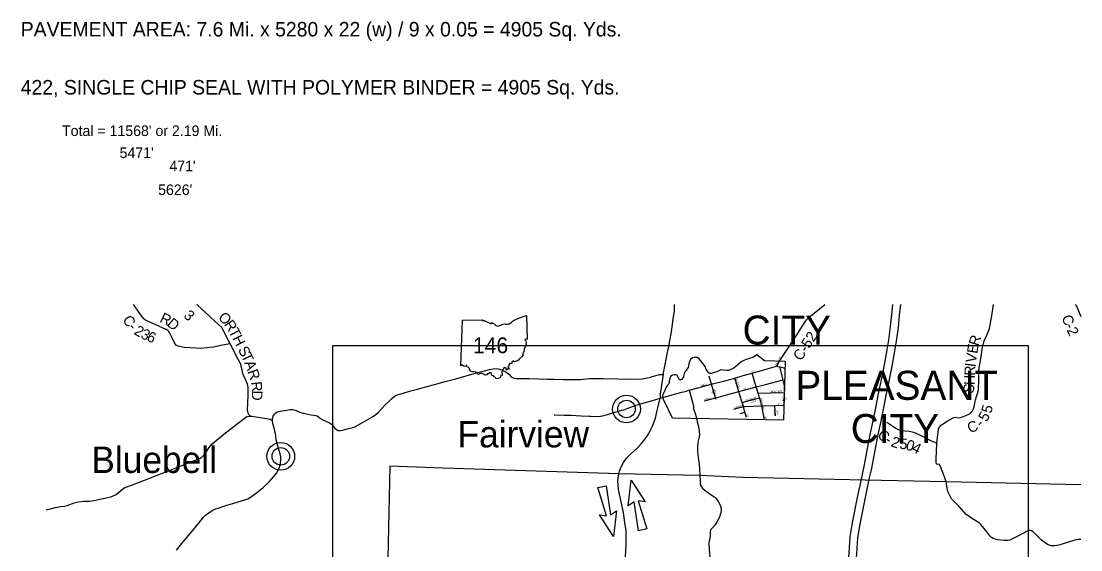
# Model space of a CAD drawing. Extents: x -452339 to 6403467, y -1 to 1814750.
# Drawn here: x 36134 to 96309, y 1629997 to 1660005 of the extents above; entities that cross this region are included whole.
import ezdxf

# ---------------------------------------------------------------- set-up
doc = ezdxf.new("R2010")
doc.units = 0
for name, color, linetype in [('Default', 7, 'Continuous'), ('GM_X_Adjacent_County_Text', 7, 'Continuous'), ('GM_X_County', 7, 'Continuous'), ('GM_X_County_Road', 7, 'Continuous'), ('GM_X_County_Road_Text', 7, 'Continuous'), ('GM_X_Minor_Lake', 7, 'Continuous'), ('GM_X_Minor_River', 7, 'Continuous'), ('GM_X_Minor_River_Text', 7, 'Continuous'), ('GM_X_Section_Text', 7, 'Continuous')]:
    doc.layers.add(name, color=color, linetype=linetype)

msp = doc.modelspace()

# ---------------------------------------------------------------- linework, layer by layer
at = {"layer": 'Default'}
for p, q in [((61109, 1640448), (61193, 1643031)), ((53831, 1602105), (53831, 1641599)), ((53831, 1641599), (93325, 1641599)), ((93325, 1641599), (93325, 1602105)), ((70605, 1632494), (70778, 1633955)), ((70778, 1633955), (71573, 1632718)), ((68885, 1633528), (69347, 1633635)), ((69372, 1631934), (68885, 1633528)), ((69347, 1633635), (69606, 1631987)), ((70941, 1632721), (70605, 1632494)), ((71200, 1631074), (70941, 1632721)), ((71573, 1632718), (71173, 1632774)), ((71173, 1632774), (71662, 1631180)), ((69768, 1630753), (68973, 1631991)), ((68973, 1631991), (69372, 1631934)), ((69606, 1631987), (69940, 1632213)), ((69940, 1632213), (69768, 1630753)), ((71662, 1631180), (71200, 1631074))]:
    msp.add_line(p, q, dxfattribs=at)
for points in [[(48004, 1641692), (47778, 1641649), (47475, 1641598), (47048, 1641504), (46704, 1641469), (46345, 1641431), (46062, 1641436), (45400, 1641486), (45045, 1641560), (44962, 1641600), (44858, 1641708), (44688, 1642065), (44573, 1642301), (44522, 1642390), (44470, 1642442), (44374, 1642494), (43188, 1643039), (43100, 1643111), (42961, 1643288), (42511, 1643927)], [(49155, 1637583), (49065, 1637680), (49017, 1637756), (48994, 1637916), (49020, 1638748), (49018, 1639208), (48987, 1639392), (48884, 1639621), (48737, 1639957), (48659, 1640298), (48584, 1640566), (48441, 1640839), (48004, 1641692), (47601, 1642470), (47530, 1642614), (47355, 1642775), (46401, 1643651), (46104, 1643927)], [(79219, 1640744), (79560, 1641260), (80079, 1642054), (80574, 1642824), (80729, 1643050), (80866, 1643177), (81773, 1643927)], [(88665, 1633859), (88577, 1634139), (88341, 1634720), (88269, 1634863), (88136, 1634833), (88093, 1634926), (88088, 1635126), (88134, 1636049), (88231, 1636836), (88268, 1636932), (88402, 1637086), (88719, 1637307), (89052, 1637491), (89152, 1637518), (89264, 1637504), (89419, 1637490), (89587, 1637549), (89960, 1637700), (90068, 1637783), (90153, 1637894), (90214, 1638009), (90281, 1638216), (90336, 1638512), (90494, 1639063), (90527, 1639712), (90527, 1640133), (90544, 1640343), (90603, 1640605), (90645, 1640975), (90721, 1641497), (90755, 1641657), (90830, 1641860), (90965, 1642180), (91032, 1642306), (91117, 1642567), (91251, 1643283), (91345, 1643927)], [(95995, 1643927), (96039, 1643881), (96091, 1643783), (96309, 1643236)], [(61193, 1643031), (62337, 1643047), (62320, 1643016), (62427, 1643010), (62542, 1642954), (62639, 1642920), (62758, 1642838), (62829, 1642838), (62859, 1642906), (62913, 1642854), (62978, 1642845), (63090, 1642721), (63182, 1642694), (63293, 1642737), (63374, 1642744), (63435, 1642785), (63592, 1642821), (63636, 1642800), (63719, 1642805), (63761, 1642820), (63834, 1642806), (63961, 1642900), (64092, 1643010), (64295, 1643115), (64596, 1643214), (64836, 1643302), (64870, 1641962)], [(64870, 1641962), (64835, 1641943), (64780, 1641952), (64744, 1641915), (64789, 1641852), (64810, 1641786), (64791, 1641713), (64810, 1641653), (64798, 1641602), (64763, 1641552), (64751, 1641504), (64722, 1641454), (64724, 1641425), (64696, 1641404), (64701, 1641319), (64687, 1641273), (64692, 1641233), (64646, 1641223), (64657, 1641189), (64628, 1641163), (64634, 1641120), (64601, 1641091), (64633, 1641035), (64608, 1641017), (64587, 1640949), (64528, 1640935), (64413, 1640811), (64371, 1640763), (64325, 1640751), (64299, 1640703), (64243, 1640703), (64156, 1640669), (64101, 1640727), (64004, 1640657), (63992, 1640576), (63870, 1640579), (63874, 1640538), (63847, 1640527), (63822, 1640486), (63836, 1640413), (63778, 1640395), (63785, 1640353), (63823, 1640328), (63839, 1640247), (63778, 1640263), (63728, 1640195), (63676, 1640211), (63692, 1640268), (63605, 1640338), (63523, 1640283), (63480, 1640194), (63479, 1640134), (63417, 1640098), (63457, 1640015), (63450, 1639957), (63451, 1639901), (63374, 1639904), (63327, 1639755)], [(63327, 1639755), (63194, 1639727), (63102, 1639710), (63069, 1639777), (63003, 1639813), (62959, 1639880), (62864, 1639890), (62841, 1639983), (62831, 1640058), (62701, 1640040), (62665, 1639994), (62619, 1639981), (62592, 1639935), (62529, 1639931), (62461, 1639909), (62417, 1639954), (62306, 1640000), (62256, 1640024), (62152, 1639988), (62130, 1639944), (62048, 1639963), (62028, 1640012), (61978, 1640026), (61967, 1640077), (61860, 1640105), (61778, 1640094), (61633, 1640135), (61624, 1640203), (61575, 1640286), (61550, 1640343), (61459, 1640386), (61440, 1640454), (61411, 1640453), (61384, 1640425), (61282, 1640412), (61242, 1640440), (61185, 1640488), (61109, 1640448)], [(70081, 1634303), (70120, 1634463), (70215, 1634704), (70336, 1634949), (70516, 1635200), (70731, 1635430), (71117, 1635766), (71337, 1636006), (71538, 1636247), (71708, 1636487), (71854, 1636742), (71988, 1637018), (72151, 1637464), (72234, 1637828), (72285, 1638049), (72430, 1638598)], [(70460, 1637986), (70540, 1638015), (71060, 1638201), (72178, 1638526), (72430, 1638598)], [(66393, 1637662), (66445, 1637657), (66979, 1637647), (67369, 1637631), (67928, 1637609), (68389, 1637590), (68457, 1637588), (68939, 1637572), (69038, 1637577), (69059, 1637578), (69291, 1637644), (70247, 1637917), (70320, 1637938), (70349, 1637947), (70460, 1637986)], [(37545, 1632284), (37617, 1632291), (37873, 1632339), (38068, 1632392), (38381, 1632453), (38592, 1632478), (38751, 1632510), (39141, 1632661), (39373, 1632722), (39714, 1632756), (40023, 1632756), (40259, 1632797), (40600, 1632878), (41047, 1632959), (41291, 1633025), (41535, 1633130), (41779, 1633350), (41982, 1633521), (42453, 1633688), (44498, 1634480), (46292, 1635198), (46404, 1635269), (46560, 1635449), (46741, 1635698), (46812, 1635796), (46977, 1636011), (47633, 1636553), (48721, 1637397), (48948, 1637556), (49060, 1637588), (49155, 1637583)], [(49155, 1637583), (49224, 1637579), (50061, 1637457)], [(50061, 1637457), (50065, 1637456), (50248, 1637411), (50405, 1637335)], [(85301, 1637235), (85808, 1636893), (85931, 1636820), (86121, 1636769), (86324, 1636751), (86583, 1636728), (86802, 1636677), (87068, 1636566), (87726, 1636222), (88134, 1636049)], [(70407, 1628954), (70498, 1630258), (70482, 1631065), (70417, 1631541), (70336, 1632117), (70063, 1633422), (70030, 1633700), (70026, 1633888), (70041, 1634073), (70081, 1634303)], [(96309, 1630588), (96302, 1630589), (96166, 1630579), (95962, 1630549), (95069, 1630265), (94825, 1630220), (94633, 1630225), (94422, 1630300), (94078, 1630551), (93595, 1631008), (93504, 1631073), (93452, 1631098), (93396, 1631102), (93300, 1631075), (92666, 1630733), (92353, 1630576), (92281, 1630549), (92165, 1630534), (91934, 1630532), (91575, 1630572), (91336, 1630634), (91241, 1630691), (91134, 1630792), (90913, 1631090), (90716, 1631345), (90637, 1631433), (90530, 1631523), (90253, 1631693), (89935, 1631897), (89797, 1632010), (89666, 1632159), (89402, 1632446), (88959, 1632899), (88759, 1633298), (88740, 1633373), (88729, 1633494), (88705, 1633632), (88665, 1633859)]]:
    msp.add_lwpolyline(points, dxfattribs=at)
at = {"layer": 'GM_X_County_Road'}
for points in [[(72877, 1641384), (72888, 1641441), (73064, 1642369), (73169, 1643096), (73230, 1643569), (73226, 1643927)], [(83847, 1633999), (84004, 1634725), (84181, 1635626), (84354, 1636536), (84520, 1637315), (84663, 1638065), (84822, 1638854), (84988, 1639653), (85157, 1640506), (85296, 1641235), (85415, 1641911), (85511, 1642672), (85575, 1643336), (85643, 1643927)], [(84278, 1633907), (84435, 1634637), (84613, 1635543), (84785, 1636449), (84952, 1637228), (85095, 1637980), (85253, 1638765), (85419, 1639565), (85589, 1640422), (85729, 1641156), (85850, 1641845), (85948, 1642623), (86013, 1643289), (86086, 1643927)], [(72596, 1639942), (72877, 1641384)], [(44962, 1629983), (45258, 1630347), (45526, 1630675), (45826, 1631031), (46220, 1631517), (46488, 1631844), (46595, 1631954), (46793, 1632100), (46984, 1632223), (47127, 1632297), (47194, 1632320), (47314, 1632363), (47753, 1632508), (48144, 1632617), (48706, 1632788), (48889, 1632850), (49001, 1632896), (49156, 1632994), (49501, 1633230), (49877, 1633527), (50218, 1633856), (50486, 1634156), (50632, 1634350), (50726, 1634515), (50796, 1634696), (50853, 1634901), (50883, 1635098), (50876, 1635302), (50826, 1635506), (50705, 1635877), (50643, 1636085), (50621, 1636225), (50598, 1636489), (50564, 1636657), (50513, 1636852), (50433, 1637156), (50405, 1637335), (50410, 1637456), (50444, 1637577), (50515, 1637694), (50586, 1637779), (50677, 1637824), (50837, 1637870), (51200, 1637930), (51396, 1637965), (51544, 1637958), (51745, 1637897), (51958, 1637815), (52151, 1637757), (52416, 1637696), (52584, 1637662), (52752, 1637644), (52869, 1637626), (52941, 1637598), (53010, 1637543), (53099, 1637464), (53264, 1637374), (53477, 1637288), (53638, 1637210), (53751, 1637123), (53861, 1636992), (53967, 1636865), (54039, 1636818), (54128, 1636779), (54264, 1636769), (54380, 1636786), (54511, 1636820), (54715, 1636874), (54974, 1636933), (55074, 1636975), (55185, 1637036), (55388, 1637147), (55690, 1637323), (56079, 1637548), (56266, 1637678), (56428, 1637816), (56637, 1638031), (56807, 1638221), (56993, 1638404), (57167, 1638574), (57310, 1638704), (57389, 1638757), (57508, 1638799), (57768, 1638874), (58182, 1638995), (58645, 1639125), (59167, 1639267), (59614, 1639389), (60213, 1639548), (60811, 1639708), (61401, 1639871), (61999, 1640034), (62438, 1640152), (62721, 1640235), (62933, 1640274), (63141, 1640280), (63301, 1640258), (63462, 1640200), (63671, 1640090), (63825, 1639964), (63963, 1639825), (64035, 1639774), (64116, 1639743), (64244, 1639729), (64524, 1639724), (64977, 1639717), (65521, 1639704), (66009, 1639690), (66402, 1639682), (66898, 1639672), (67358, 1639666), (67879, 1639660), (68414, 1639719), (69183, 1639719), (70014, 1639703), (70754, 1639679), (71405, 1639706), (71702, 1639755), (71873, 1639803)], [(71873, 1639803), (71972, 1639831), (72402, 1639942), (72596, 1639942)], [(72596, 1639942), (72596, 1639942), (72482, 1639219)], [(72482, 1639219), (72460, 1639075), (72416, 1638868), (72430, 1638598)], [(72430, 1638598), (72579, 1638638), (72633, 1638654)], [(72633, 1638654), (73649, 1638937), (73908, 1639010), (74052, 1639053)], [(74052, 1639053), (74060, 1639056), (74308, 1638178), (74310, 1638095), (74320, 1638000), (74409, 1637734), (74461, 1637541)], [(74461, 1637541), (74484, 1637453), (74547, 1637187), (74617, 1636896), (74647, 1636549), (74629, 1636417), (74569, 1636107), (74539, 1635826), (74548, 1635591), (74588, 1635210), (74633, 1634889), (74673, 1634207)], [(74673, 1634207), (74688, 1633903), (74695, 1633799), (74701, 1633741), (74713, 1633676), (74733, 1633620), (74833, 1633496), (74982, 1633358), (75240, 1633179), (75438, 1633046), (75550, 1632957), (75641, 1632850), (75730, 1632716), (75810, 1632577), (75863, 1632430), (75886, 1632234), (75855, 1632034), (75788, 1631851), (75662, 1631612), (75546, 1631417), (75392, 1631241), (75288, 1631134), (75253, 1631036), (75263, 1630901), (75260, 1630766), (75228, 1630590), (75203, 1630486), (75181, 1630373), (75200, 1630017), (75235, 1629588)], [(78458, 1611106), (81172, 1618520), (82232, 1621509), (82364, 1621883), (82549, 1622417), (82699, 1623014), (82840, 1623835), (82930, 1624594), (82960, 1625758), (83025, 1627609), (83057, 1628684), (83149, 1629798), (83211, 1630732), (83338, 1631537), (83625, 1632957), (83847, 1633999)], [(78871, 1610955), (81586, 1618371), (82647, 1621362), (82780, 1621738), (82971, 1622291), (83130, 1622923), (83275, 1623772), (83370, 1624562), (83400, 1625745), (83465, 1627595), (83496, 1628659), (83587, 1629766), (83649, 1630683), (83771, 1631460), (84056, 1632867), (84278, 1633907)]]:
    msp.add_lwpolyline(points, dxfattribs=at)
at = {"layer": 'GM_X_County_Road_Text'}
for centre, radius in [((70509, 1637987), 786), ((70509, 1637987), 498), ((50876, 1635302), 786), ((50876, 1635302), 498)]:
    msp.add_circle(centre, radius, dxfattribs=at)
at = {"layer": 'GM_X_Minor_Lake'}
for points in [[(74060, 1639056), (75340, 1639407), (75400, 1639423), (76095, 1639584), (76661, 1639748), (77131, 1639884), (77646, 1640030), (78503, 1640272), (79019, 1640418), (79043, 1640418), (79083, 1640417), (79103, 1640412), (79111, 1640410)], [(79043, 1640418), (79219, 1640744)], [(79111, 1640410), (79226, 1640381), (79509, 1640308)], [(79460, 1638232), (79465, 1638284), (79488, 1638860), (79488, 1638920), (79489, 1639312), (79405, 1639633), (79401, 1639649), (79226, 1640381)], [(75600, 1638522), (75571, 1638621), (75340, 1639407), (75209, 1639851)], [(78180, 1638206), (78131, 1638392), (78064, 1638615), (77984, 1638884), (77877, 1639242), (77646, 1640030)], [(76184, 1638788), (76187, 1638789), (76893, 1638978), (77453, 1639128), (77877, 1639242), (78409, 1639385), (79401, 1639649)], [(77323, 1637513), (77237, 1637816), (77149, 1638128), (77077, 1638364), (76951, 1638778), (76893, 1638978), (76763, 1639420), (76661, 1639748)], [(74942, 1638446), (75571, 1638621), (75866, 1638703), (76184, 1638788)], [(77077, 1638364), (78064, 1638615)], [(77984, 1638884), (79488, 1638920)], [(76599, 1637978), (76951, 1638082), (77092, 1638116), (77096, 1638116)], [(77096, 1638116), (77149, 1638128), (77215, 1638135), (78192, 1638161), (78260, 1638162), (78942, 1638185), (79408, 1638201), (79460, 1638232)], [(78342, 1637378), (78192, 1638161), (78181, 1638205), (78180, 1638206)], [(78974, 1637594), (78942, 1638185)], [(76955, 1637738), (77237, 1637816)]]:
    msp.add_lwpolyline(points, dxfattribs=at)
at = {"layer": 'GM_X_Minor_River_Text'}
msp.add_lwpolyline([(72581, 1638784), (72612, 1638851), (72654, 1638950), (72711, 1639065), (72764, 1639202), (72817, 1639281), (72851, 1639358), (72909, 1639426), (72939, 1639464), (72943, 1639510), (72954, 1639601), (72969, 1639658), (72988, 1639750), (73030, 1639841), (73061, 1639887), (73129, 1639932), (73213, 1639955), (73293, 1639955), (73365, 1639936), (73426, 1639803), (73453, 1639727), (73567, 1639647), (73616, 1639658), (73670, 1639681), (73746, 1639769), (73765, 1639841), (73776, 1639917), (73811, 1640001), (73830, 1640077), (73898, 1640163), (73960, 1640246), (74023, 1640343), (74050, 1640468), (74085, 1640634), (74120, 1640752), (74168, 1640842), (74251, 1640918), (74348, 1640939), (74522, 1640932), (74591, 1640884), (74660, 1640807), (74757, 1640662), (74917, 1640461), (74972, 1640371), (75000, 1640288), (75062, 1640156), (75159, 1640052), (75249, 1640018), (75360, 1640018), (75533, 1640080), (75693, 1640142), (75845, 1640218), (75914, 1640225), (76025, 1640212), (76198, 1640191), (76330, 1640191), (76399, 1640225), (76462, 1640253), (76614, 1640329), (76732, 1640433), (76864, 1640551), (77002, 1640669), (77162, 1640752), (77328, 1640821), (77522, 1640877), (77723, 1640946), (77917, 1641084), (78354, 1640739), (79528, 1640699), (79427, 1637357), (73128, 1637476), (72610, 1638536), (72585, 1638613), (72572, 1638664), (72566, 1638718)], close=True, dxfattribs=at)
at = {"layer": 'GM_X_Section_Text'}
for p, q in [((57065, 1634739), (57047, 1633854)), ((60098, 1634638), (57065, 1634739)), ((70081, 1634303), (60098, 1634638)), ((57047, 1633854), (56938, 1628608)), ((74673, 1634207), (70081, 1634303)), ((77115, 1634109), (74673, 1634207)), ((84062, 1633953), (77115, 1634109)), ((88665, 1633859), (84062, 1633953)), ((96309, 1633679), (88665, 1633859))]:
    msp.add_line(p, q, dxfattribs=at)

# ---------------------------------------------------------------- texts
at = {"layer": 'Default'}
for s, height, p in [('PAVEMENT AREA: 7.6 Mi. x 5280 x 22 (w) / 9 x 0.05 = 4905 Sq. Yds.', 823.68, (36109, 1659138)), ('422, SINGLE CHIP SEAL WITH POLYMER BINDER = 4905 Sq. Yds.', 823.68, (36109, 1655843)), ('146', 895.5, (61789, 1641156))]:
    msp.add_text(s, height=height, dxfattribs=at).set_placement(p)
at = {"layer": 'GM_X_Adjacent_County_Text'}
for s, height, p in [('CITY', 1647.4, (77103, 1641646)), ('PLEASANT', 1647.4, (80100, 1638510)), ('Fairview', 1500, (60914, 1635810)), ('CITY', 1647.4, (83246, 1636059)), ('Bluebell', 1500, (40117, 1634357))]:
    msp.add_text(s, height=height, rotation=0.00001, dxfattribs=at).set_placement(p)
at = {"layer": 'GM_X_County'}
for s, rotation, p in [('R', 334.4718, (43958, 1642949)), ('3', 317.07085, (45319, 1643238)), ('O', 313.68749, (47282, 1643155)), ('C', 304.56803, (41862, 1643056)), ('D', 320.25553, (44369, 1642758)), ('R', 303.68141, (47629, 1642794)), ('C', 291.42744, (95205, 1643200)), ('-', 292.46574, (95389, 1642730)), ('-', 309.20704, (42173, 1642608)), ('2', 328.49868, (42494, 1642272)), ('3', 335.37773, (42879, 1642042)), ('6', 335.63823, (43217, 1641887)), ('T', 297.63839, (47894, 1642399)), ('H', 297.35357, (48102, 1642002)), ('C-52', 56.97613, (80427, 1640679)), ('R', 72.19019, (90493, 1641525)), ('2', 294.92335, (95495, 1642476)), ('E', 81.08863, (90429, 1641105)), ('S', 297.21105, (48429, 1641369)), ('T', 294.8859, (48611, 1641015)), ('V', 81.41474, (90350, 1640584)), ('A', 290.4484, (48796, 1640619)), ('R', 87.69269, (90298, 1639865)), ('I', 82.02776, (90316, 1640342)), ('R', 288.84596, (48979, 1640129)), ('H', 88.18533, (90281, 1639339)), ('R', 276.41821, (49186, 1639520)), ('S', 78.36951, (90186, 1638831)), ('D', 269.22404, (49240, 1639050)), ('5', 75.03859, (91220, 1637707)), ('5', 58.95899, (90958, 1637222)), ('C', 324.60479, (84711, 1636394)), ('C', 23.12274, (90016, 1636600)), ('-', 41.47076, (90645, 1636906)), ('-', 326.65353, (85132, 1636096)), ('2', 340.70812, (85482, 1635889)), ('5', 355.42903, (85995, 1635732)), ('0', 341.895, (86327, 1635710)), ('4', 333.61415, (86657, 1635604))]:
    msp.add_text(s, height=600, rotation=rotation, dxfattribs=at).set_placement(p)
at = {"layer": 'GM_X_Minor_River'}
for s, rotation, p in [('EAST ST', 62.48579, (79036, 1640428)), ('CHURCH', 286.60825, (76683, 1639756)), ('ST', 14.03624, (77630, 1640049)), ('MAIN', 15.52473, (74743, 1639266)), ('ST', 14.03624, (77146, 1639064)), ('HIGH', 14.82754, (74955, 1638474)), ('ST', 284.93778, (75313, 1638981)), ('MILL', 287.3515, (75460, 1639096)), ('NO NAME', 14.47088, (77278, 1638430)), ('ORCHARD', 284.44611, (78091, 1638603)), ('JADWIN', 1.0803, (78646, 1638924)), ('ST', 0.00001, (79157, 1638941)), ('EAST', 86.73128, (79456, 1638432)), ('ST', 90, (79636, 1638519)), ('W', 14.69692, (76618, 1638008)), ('A', 14.68294, (76728, 1638037)), ('L', 14.69653, (76814, 1638059)), ('N', 14.69351, (76882, 1638077)), ('U', 14.69351, (76967, 1638099)), ('T', 12.41916, (77051, 1638121)), ('2 ST', 12.52581, (77597, 1638343)), ('BUSH', 91.54737, (78963, 1637612)), ('ST', 3.57463, (79094, 1638211)), ('ST', 287.35676, (77308, 1637688)), ('ST', 280.62667, (78338, 1637554)), ('AVE', 91.97391, (79134, 1637653))]:
    msp.add_text(s, height=100, rotation=rotation, dxfattribs=at).set_placement(p)
at = {"layer": 'GM_X_Section_Text'}
for s, p in [("Total = 11568' or 2.19 Mi.", (38454, 1653486)), ("5471'", (41723, 1652236)), ("471'", (44551, 1651488)), ("5626'", (43912, 1650137))]:
    msp.add_text(s, height=600, dxfattribs=at).set_placement(p)

doc.saveas('drawing.dxf')
